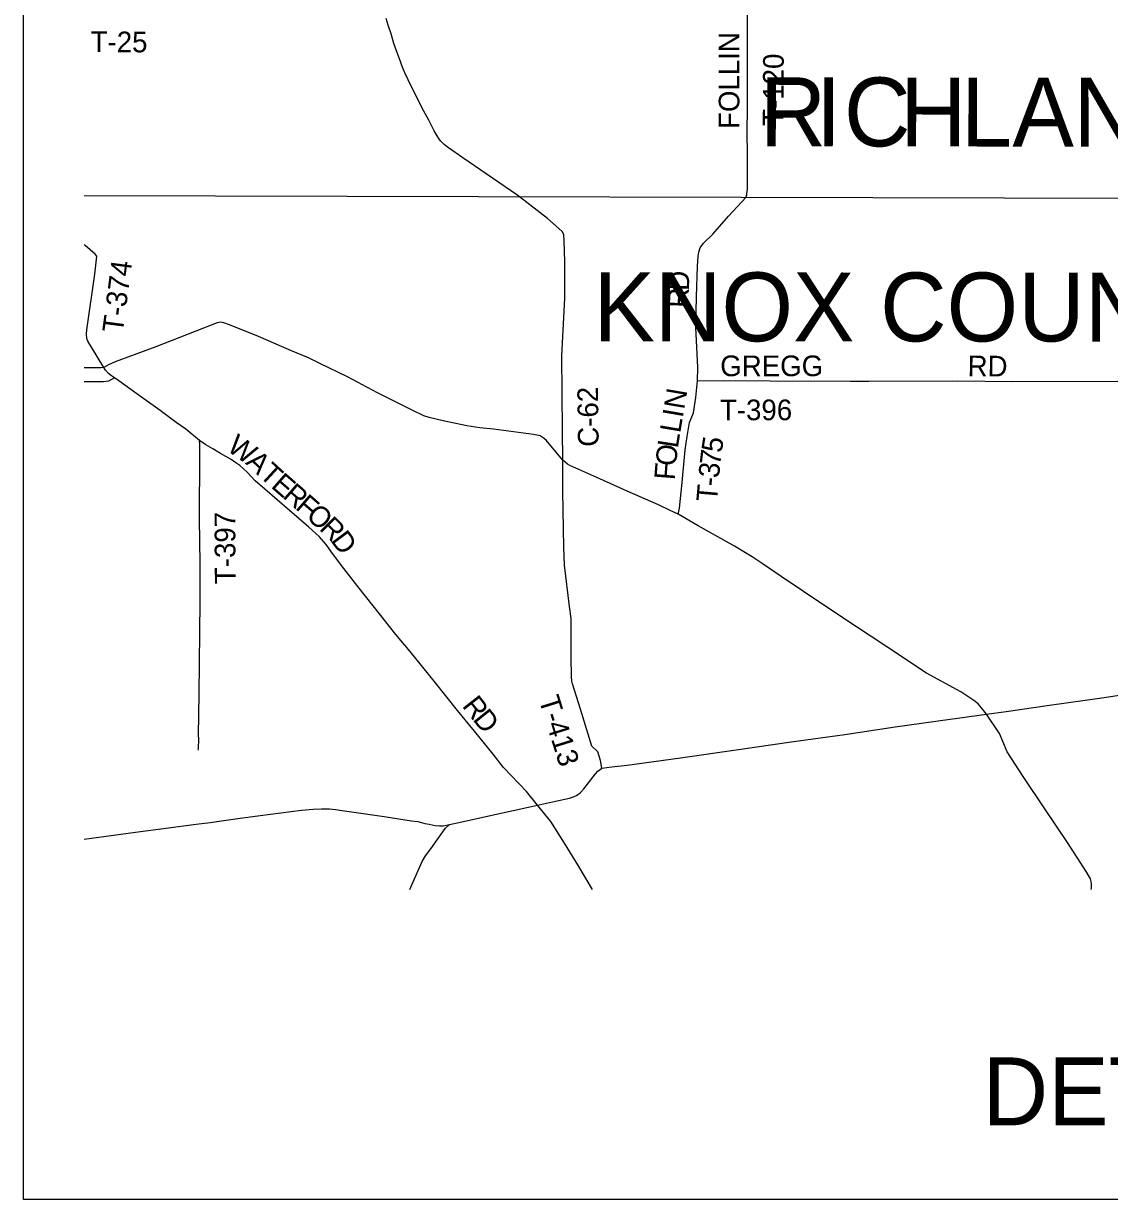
# Model space of a CAD drawing. Extents: x 40529 to 41139, y 15164 to 15584.
# Drawn here: x 40528.7 to 40618.2, y 15164.3 to 15261.3 of the extents above; entities that cross this region are included whole.
import ezdxf

# ---------------------------------------------------------------- set-up
doc = ezdxf.new("R2010")
doc.units = 0
for name, color, linetype in [('GM_X_County_Road', 7, 'Continuous'), ('GM_X_County_Road_Text', 7, 'Continuous'), ('GM_X_County_Text', 7, 'Continuous'), ('GM_X_Township_Road', 7, 'Continuous'), ('GM_X_Township_Road_Text', 7, 'Continuous'), ('SC_Scratch1', 7, 'Continuous'), ('SH_Cut_Line', 7, 'Continuous'), ('SH_Text', 7, 'Continuous')]:
    doc.layers.add(name, color=color, linetype=linetype)

msp = doc.modelspace()

# ---------------------------------------------------------------- linework, layer by layer
at = {"layer": 'GM_X_County_Road'}
for points in [[(40569.58, 15247.022), (40569.336, 15247.193), (40567.346, 15248.552), (40564.885, 15250.232), (40563.708, 15251.057), (40563.484, 15251.227), (40563.343, 15251.347), (40563.148, 15251.536), (40563.085, 15251.601), (40562.969, 15251.749), (40562.714, 15252.136), (40562.528, 15252.457), (40562.274, 15252.954), (40562.076, 15253.352), (40561.669, 15254.087), (40561.281, 15254.831), (40560.385, 15256.657), (40560.119, 15257.248), (40559.982, 15257.589), (40559.871, 15257.852), (40559.738, 15258.194), (40559.611, 15258.538), (40559.205, 15259.668), (40558.968, 15260.459), (40558.77, 15261.094), (40558.575, 15261.738)], [(40573.146, 15225.287), (40573.117, 15227.747), (40573.054, 15233.897), (40573.312, 15238.667), (40573.295, 15241.621), (40573.26, 15243.404), (40573.225, 15243.893), (40573.103, 15244.137), (40572.823, 15244.417), (40571.879, 15245.239), (40569.58, 15247.022)], [(40582.661, 15220.831), (40582.001, 15221.148), (40581.045, 15221.612), (40578.461, 15222.742), (40575.935, 15223.862), (40574.228, 15224.63), (40573.727, 15224.845), (40573.534, 15224.97), (40573.146, 15225.287), (40572.428, 15226.15), (40571.778, 15226.946), (40571.527, 15227.15), (40571.265, 15227.297), (40570.731, 15227.409), (40567.41, 15227.854), (40566.285, 15227.953), (40565.216, 15228.143), (40563.271, 15228.546), (40562.122, 15228.827), (40561.679, 15228.962), (40560.768, 15229.381), (40557.866, 15230.863), (40555.373, 15232.165), (40553.085, 15233.285), (40552.163, 15233.726), (40550.763, 15234.325), (40548.032, 15235.5), (40545.631, 15236.46), (40545.176, 15236.63), (40544.892, 15236.674), (40544.619, 15236.617), (40544.142, 15236.422), (40539.578, 15234.641), (40536.206, 15233.4), (40535.655, 15233.154), (40535.286, 15232.953)], [(40571.059, 15196.83), (40570.156, 15197.961), (40568.261, 15199.933), (40567.394, 15201.046), (40565.855, 15202.931), (40564.44, 15204.646), (40562.524, 15207.066), (40560.54, 15209.508), (40559.376, 15210.916), (40558.133, 15212.472), (40556.228, 15214.869), (40555.087, 15216.357), (40554.141, 15217.595), (40553.616, 15218.345), (40553.045, 15218.992), (40552.18, 15219.764), (40550.596, 15221.137), (40548.545, 15222.918), (40547.77, 15223.599), (40547.088, 15224.32), (40546.487, 15224.849), (40546.172, 15225.071), (40545.779, 15225.343), (40544.892, 15225.844), (40544.269, 15226.223), (40543.69, 15226.559), (40543.182, 15226.924), (40542.037, 15227.847), (40541.255, 15228.395), (40539.922, 15229.381), (40537.998, 15230.764), (40536.528, 15231.853), (40536.146, 15232.095), (40535.902, 15232.249), (40535.651, 15232.453), (40535.423, 15232.726), (40535.286, 15232.953), (40535.048, 15232.918), (40533.651, 15232.914)], [(40616.726, 15189.885), (40616.742, 15190.024), (40616.764, 15190.331), (40616.74, 15190.536), (40616.671, 15190.753), (40616.374, 15191.275), (40614.765, 15193.764), (40612.916, 15196.525), (40611.124, 15199.207), (40609.789, 15201.23), (40609.167, 15202.739), (40608.086, 15204.34), (40607.683, 15204.874), (40607.392, 15205.185), (40607.038, 15205.466), (40605.965, 15206.194), (40603.133, 15207.722), (40599.877, 15209.898), (40596.085, 15212.402), (40592.988, 15214.465), (40591.166, 15215.7), (40589.583, 15216.777), (40588.763, 15217.332), (40588.205, 15217.661), (40587.294, 15218.216), (40586.19, 15218.827), (40584.3, 15219.88), (40582.661, 15220.831)], [(40575.589, 15189.885), (40574.376, 15191.924), (40573.268, 15193.708), (40572.145, 15195.496), (40571.059, 15196.83)]]:
    msp.add_lwpolyline(points, dxfattribs=at)
at = {"layer": 'GM_X_Township_Road'}
for points in [[(40588.237, 15246.975), (40588.284, 15247.089), (40588.309, 15247.181), (40588.329, 15247.274), (40588.354, 15247.461), (40588.365, 15247.648), (40588.374, 15248.115), (40588.366, 15249.328), (40588.37, 15250.26), (40588.358, 15252.59), (40588.377, 15254.173), (40588.38, 15255.106), (40588.388, 15256.596), (40588.379, 15257.247), (40588.368, 15258.178), (40588.363, 15260.882), (40588.374, 15262.279), (40588.373, 15262.453)], [(40582.661, 15220.831), (40582.773, 15221.344), (40582.983, 15223.463), (40583.226, 15226.152), (40583.404, 15227.257), (40583.594, 15228.408), (40583.911, 15229.209), (40584.105, 15230.458), (40584.244, 15231.84), (40584.283, 15232.934), (40584.107, 15236.256), (40584.168, 15238.773), (40584.263, 15241.302), (40584.295, 15242.133), (40584.362, 15242.452), (40584.475, 15242.806), (40584.746, 15243.205), (40585.517, 15243.948), (40586.812, 15245.418), (40587.912, 15246.611), (40588.237, 15246.975)], [(40535.286, 15232.953), (40534.738, 15233.84), (40533.95, 15235.113), (40533.87, 15235.34), (40533.835, 15235.693), (40533.88, 15236.035), (40534.529, 15240.633), (40534.633, 15241.633), (40534.694, 15242.138), (40534.56, 15242.303), (40533.736, 15243.014), (40533.651, 15243.082)], [(40536.146, 15232.095), (40535.655, 15231.825), (40535.464, 15231.781), (40535.259, 15231.759), (40533.651, 15231.759)], [(40584.244, 15231.84), (40586.472, 15231.863), (40590.235, 15231.855), (40596.862, 15231.809), (40598.399, 15231.809), (40605.678, 15231.855), (40610.272, 15231.793), (40618.87, 15231.824), (40625.194, 15231.789)], [(40543.23, 15213.703), (40543.227, 15213.817), (40543.221, 15213.989), (40543.232, 15214.522), (40543.225, 15215.338), (40543.228, 15216.779), (40543.164, 15220.463), (40543.196, 15225.765), (40543.204, 15226.616), (40543.182, 15226.924)], [(40576.371, 15199.887), (40576.255, 15200.517), (40576.036, 15201.231), (40575.542, 15201.699), (40574.59, 15204.748), (40573.937, 15206.852), (40573.879, 15207.08), (40573.855, 15207.433), (40573.839, 15209.061), (40573.843, 15211.84), (40573.842, 15212.239), (40573.68, 15213.229), (40573.273, 15216.633), (40573.223, 15218.124), (40573.153, 15222.714), (40573.146, 15225.287)], [(40543.059, 15201.377), (40543.092, 15201.489), (40543.11, 15202.313), (40543.096, 15202.614), (40543.153, 15205.983), (40543.232, 15213.646), (40543.23, 15213.703)], [(40608.086, 15204.34), (40609.716, 15204.564), (40613.291, 15205.097), (40617.599, 15205.68), (40621.398, 15206.257)], [(40576.371, 15199.887), (40577.186, 15199.989), (40578.438, 15200.139), (40582.862, 15200.755), (40587.631, 15201.444), (40591.983, 15202.06), (40596.403, 15202.671), (40600.561, 15203.288), (40605.092, 15203.928), (40608.086, 15204.34)], [(40571.059, 15196.83), (40572.286, 15197.112), (40573.688, 15197.427), (40573.935, 15197.495), (40574.258, 15197.64), (40574.566, 15197.869), (40574.877, 15198.189), (40575.847, 15199.421), (40576.041, 15199.634), (40576.371, 15199.887)], [(40533.651, 15194.045), (40537.879, 15194.623), (40542.886, 15195.273), (40544.049, 15195.399), (40544.996, 15195.559), (40546.345, 15195.748), (40548.183, 15195.981), (40551.58, 15196.423), (40552.55, 15196.515), (40553.244, 15196.539), (40553.903, 15196.529), (40554.379, 15196.486), (40554.932, 15196.408), (40558.395, 15195.892), (40560.671, 15195.549), (40561.181, 15195.482), (40561.763, 15195.336), (40562.127, 15195.273), (40562.607, 15195.166), (40562.971, 15195.142), (40563.272, 15195.147), (40563.791, 15195.234)], [(40563.791, 15195.234), (40564.8, 15195.457), (40568.162, 15196.219), (40571.059, 15196.83)], [(40560.517, 15189.885), (40560.695, 15190.274), (40561.542, 15192.201), (40561.814, 15192.657), (40562.249, 15193.224), (40562.762, 15193.973), (40563.238, 15194.637), (40563.461, 15194.938), (40563.791, 15195.234)]]:
    msp.add_lwpolyline(points, dxfattribs=at)
at = {"layer": 'SC_Scratch1'}
msp.add_lwpolyline([(40528.651, 15584.313), (41138.651, 15584.313), (41138.651, 15164.313), (40528.651, 15164.313)], close=True, dxfattribs=at)
at = {"layer": 'SH_Cut_Line'}
msp.add_line((40533.651, 15247.133), (40737.651, 15246.595), dxfattribs=at)

# ---------------------------------------------------------------- texts
at = {"layer": 'GM_X_County_Road_Text'}
for s, height, rotation, p in [('C-62', 1.7063, 90.67581, (40576.102, 15226.41)), ('W', 1.706, 324.48645, (40545.342, 15226.149)), ('A', 1.706, 316.55345, (40546.903, 15225.04)), ('T', 1.706, 317.47465, (40548.015, 15223.987)), ('E', 1.706, 318.87693, (40548.99, 15223.094)), ('R', 1.706, 318.90343, (40549.952, 15222.254)), ('F', 1.706, 318.90805, (40551.008, 15221.332)), ('O', 1.706, 318.76851, (40551.875, 15220.577)), ('R', 1.706, 315.17939, (40552.984, 15219.606)), ('D', 1.706, 306.73658, (40553.934, 15218.668)), ('R', 1.706, 308.22826, (40564.781, 15205.016)), ('D', 1.706, 308.73187, (40565.658, 15203.902))]:
    msp.add_text(s, height=height, rotation=rotation, dxfattribs=at).set_placement(p)
at = {"layer": 'GM_X_County_Text'}
for s, height, rotation, p in [('R', 5.682, 359.92439, (40589.38, 15251.195)), ('I', 5.682, 359.92362, (40594.006, 15251.189)), ('C', 5.682, 359.92411, (40596.331, 15251.186)), ('H', 5.682, 359.92388, (40600.956, 15251.18)), ('L', 5.682, 359.92408, (40605.981, 15251.173)), ('A', 5.682, 359.92454, (40610.231, 15251.168)), ('N', 5.682, 359.93409, (40615.257, 15251.161)), ('KNOX COUNTY', 5.68182, 359.97216, (40575.67, 15235.106))]:
    msp.add_text(s, height=height, rotation=rotation, dxfattribs=at).set_placement(p)
at = {"layer": 'GM_X_Township_Road_Text'}
for s, height, rotation, p in [('T-25', 1.7063, 359.64652, (40534.182, 15258.963)), ('FOLLIN', 1.7063, 90, (40587.709, 15252.615)), ('T-120', 1.7063, 89.72327, (40591.342, 15252.87)), ('T-374', 1.7063, 82.42807, (40536.833, 15235.735)), ('D', 1.706, 87.53307, (40583.537, 15239.241)), ('R', 1.706, 88.59872, (40583.503, 15237.849)), ('GREGG', 1.7063, 0.00001, (40586.126, 15232.225)), ('RD', 1.7063, 359.50636, (40606.528, 15232.224)), ('N', 1.706, 80.39311, (40583.15, 15229.432)), ('T-396', 1.7063, 0.00001, (40586.101, 15228.592)), ('I', 1.706, 80.39265, (40583.033, 15228.741)), ('L', 1.706, 80.4024, (40582.82, 15227.483)), ('L', 1.706, 81.26621, (40582.627, 15226.228)), ('O', 1.706, 83.79898, (40582.468, 15224.755)), ('5', 1.706, 81.05956, (40586.238, 15225.843)), ('7', 1.706, 83.42878, (40586.12, 15224.817)), ('F', 1.706, 85.50034, (40582.378, 15223.621)), ('3', 1.706, 84.47529, (40586.02, 15223.779)), ('-', 1.706, 84.92712, (40585.958, 15223.085)), ('T', 1.706, 85.06552, (40585.848, 15221.814)), ('T-397', 1.7063, 90.28072, (40546.144, 15215.076)), ('T-413', 1.7063, 287.37102, (40571.134, 15205.577))]:
    msp.add_text(s, height=height, rotation=rotation, dxfattribs=at).set_placement(p)
at = {"layer": 'SH_Text'}
msp.add_text('DETOUR PLAN', height=5.6, dxfattribs=at).set_placement((40607.773, 15170.433))

doc.saveas('drawing.dxf')
